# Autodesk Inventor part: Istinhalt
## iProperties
Created: 2005-10
Part Number: Istinhalt
Material: Milch
Document SubType Name: Modeling
Designer: rsc
Manufacturer: Standard
Standards Organization: Custom
Kanten: brechen
Oberflächen: Ra 3,2
Radien: 2
Toleranzen: ISO 2768 - m
Author: rsc
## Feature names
1. Extrusion1
2. Abgeleiteter Körper1 [Tagging]
